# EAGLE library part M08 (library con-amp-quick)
AMP QUICK CONNECTOR
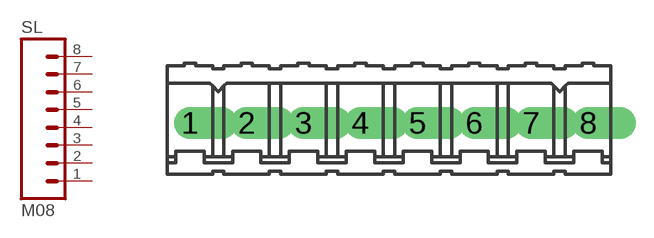
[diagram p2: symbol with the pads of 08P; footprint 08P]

Designator prefix SL

## M08  [08P]
1  1  pas
2  2  pas
3  3  pas
4  4  pas
5  5  pas
6  6  pas
7  7  pas
8  8  pas

## Footprint 08P (pad centres in mm)
AMP QUICK CONNECTOR
drill 0.914 offset: 1 -8.89,0; 2 -6.35,0; 3 -3.81,0; 4 -1.27,0; 5 1.27,0; 6 3.81,0; 7 6.35,0; 8 8.89,0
